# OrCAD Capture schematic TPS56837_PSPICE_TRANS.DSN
size C
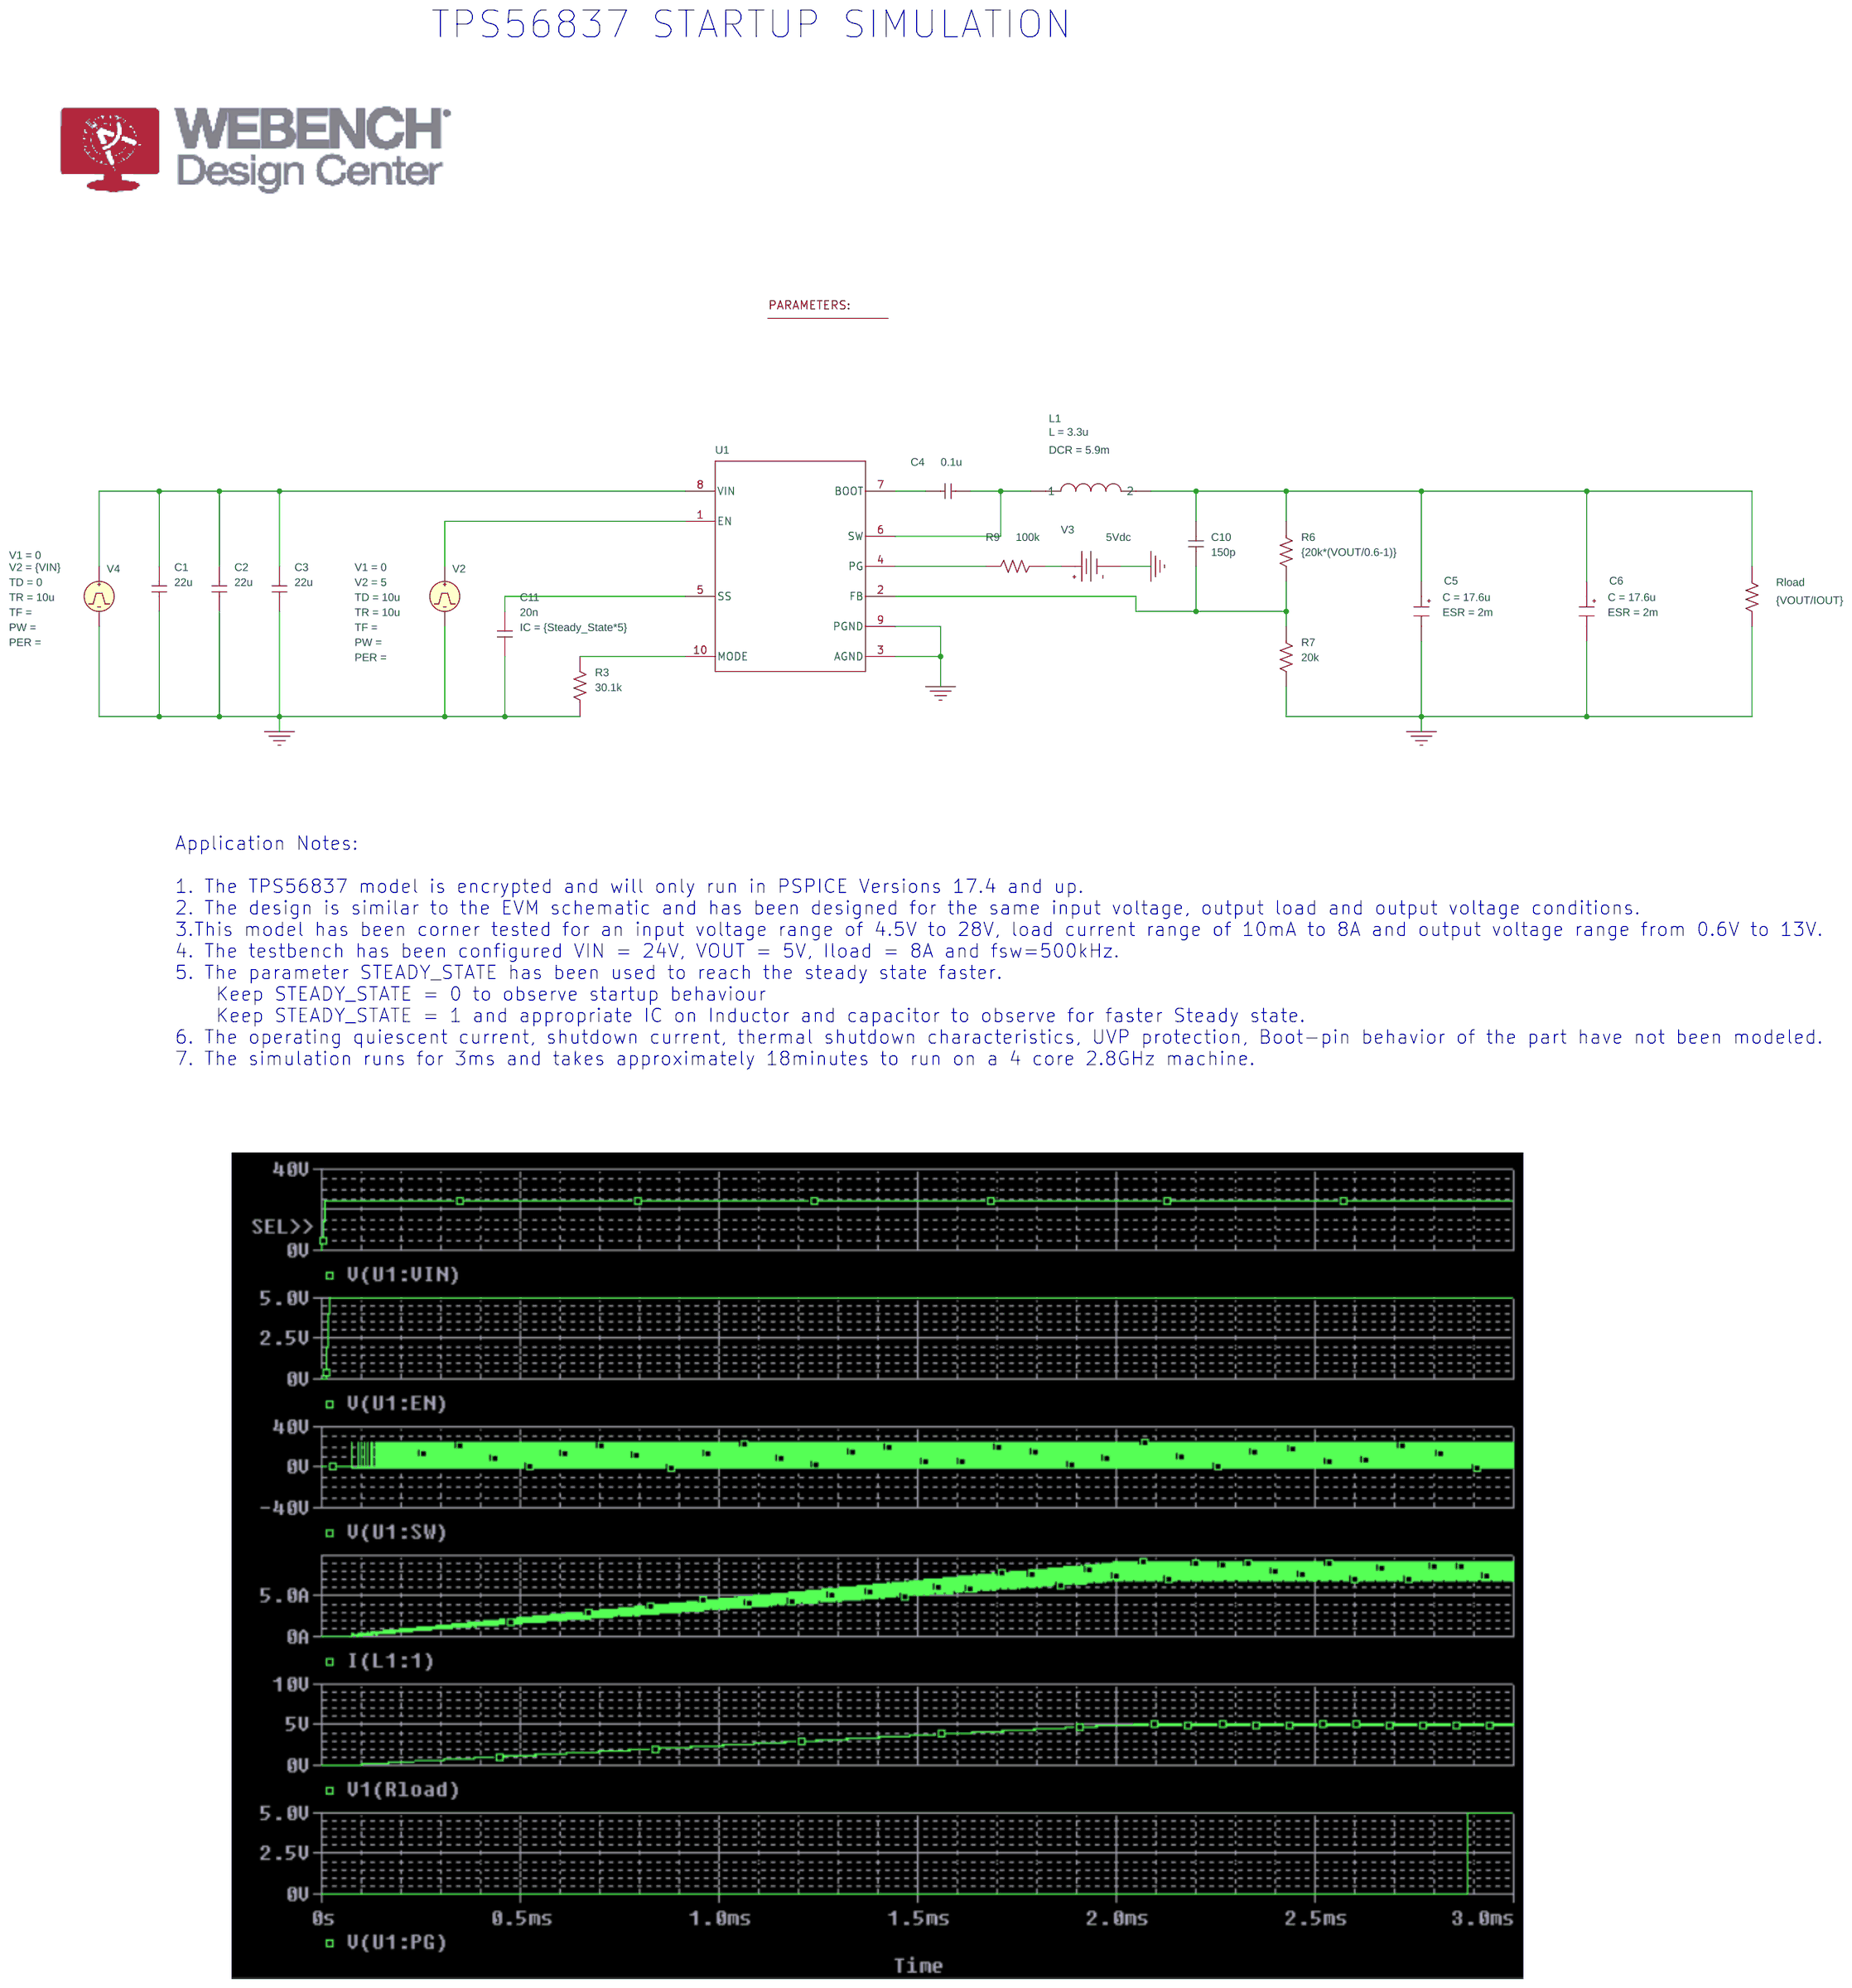
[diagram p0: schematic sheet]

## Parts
3  PARAM
C1  22u  [cap196]
C2  22u  [cap196]
C3  22u  [cap196]
C4  0.1u  [cap196]
C5  CESR
C6  CESR
C10  150p  [cap196]
C11  20n  [RAD/CK05]
L1  LDCR
R3  30.1k  [AXRC05]
R6  {20k*(VOUT/0.6-1)}  [AX/RC05]
R7  20k  [AX/RC05]
R9  100k  [AXRC05]
Rload  {VOUT/IOUT}  [AX/RC05]
U1  Value  [RPA0010A-MFG]
V2  VPULSE
V3  VDC
V4  VPULSE

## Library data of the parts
3 = PARAM: IOUT: 8; Steady_State: 0; VIN: 24; VOUT: 5
C1-C3 C10 = C: IC: 0
C4 = C: IC: 0; VC1: 5
C5 C6 = CESR_0: C: 17.6u; ESL: 0; ESR: 2m; IC: 0
C11 = C: IC: {Steady_State*5}
L1 = LDCR: DCR: 5.9m; IC: 0; L: 3.3u
R3 R6 R7 R9 Rload = R
U1 = TPS56837RPA_TRANS
V2 = VPULSE: TD: 10u; TR: 10u; V1: 0; V2: 5
V3 = VDC: DC: 5Vdc
V4 = VPULSE: TD: 0; TR: 10u; V1: 0; V2: {VIN}

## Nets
0: C1.1 C2.1 C3.1 C5.2(OUT) C6.2(OUT) C11.2 R3.1 R7.2 Rload.2 U1.3(AGND) U1.9(PGND) V2.2(-) V3.1(-) V4.2(-)
N80429: C1.2 C2.2 C3.2 U1.8(VIN) V4.1(+)
N80463: C4.2 U1.7(BOOT)
N80469: C4.1 L1.1 U1.6(SW)
N80485: C5.1(IN) C6.1(IN) C10.2 L1.2 R6.1 Rload.1
N80533: U1.1(EN) V2.1(+)
N80639: R9.2 U1.4(PG)
N80645: R9.1 V3.0(+)
N80657: C10.1 R6.2 R7.1 U1.2(FB)
N80827: C11.1 U1.5(SS)
N81009: R3.2 U1.10(MODE)

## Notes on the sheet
- TPS56837 STARTUP SIMULATION
- Application Notes:
  1. The TPS56837 model is encrypted and will only run in PSPICE Versions 17.4 and up.
  2. The design is similar to the EVM schematic and has been designed for the same input voltage, output load and output voltage conditions.
  3.This model has been corner tested for an input voltage range of 4.5V to 28V, load current range of 10mA to 8A and output voltage range from 0.6V to 13V.
  4. The testbench has been configured VIN = 24V, VOUT = 5V, Iload = 8A and fsw=500kHz.
  5. The parameter STEADY_STATE has been used to reach the steady state faster.
      Keep STEADY_STATE = 0 to observe startup behaviour
      Keep STEADY_STATE = 1 and appropriate IC on Inductor and capacitor to observe for faster Steady state.
  6. The operating quiescent current, shutdown current, thermal shutdown characteristics, UVP protection, Boot-pin behavior of the part have not been modeled.
  7. The simulation runs for 3ms and takes approximately 18minutes to run on a 4 core 2.8GHz machine.
